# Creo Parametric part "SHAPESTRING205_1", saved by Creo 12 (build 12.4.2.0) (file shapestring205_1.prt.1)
Units: Custom; MM, KILOGRAM, SECS

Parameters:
  PTC_WM_ITERATION = "0"
  PTC_WM_VERSION = "-.0"
  PTC_WM_LIFECYCLE_STATE = "In Work"
  PTC_WM_LIFECYCLE = "MO_CADDocument"
  PTC_WM_CREATED_BY = "Maximilian Roepper (Z0017RMS: MO)"
  PTC_WM_CREATED_ON = "18-Sep-26 11:36:42 AM"
  PTC_WM_MODIFIED_BY = "Maximilian Roepper (Z0017RMS: MO)"
  PTC_WM_MODIFIED_ON = "18-Sep-26 11:36:46 AM"
  PDMLINKNUMBER = "PDM000071454910"
  PTC_WM_NAME = "shapestring205_1.prt"
  PTC_WM_NUMBER = "PDM000071454910"

Other parameters: WEIGHT, WEIGHT_FACTOR, WEIGHT_ADD, _MASS_TEMP, _DIFF_TEMP, MC_ERRORS, SUPPLIER

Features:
  1. coordinate system
  2. datum plane "PRT_YZ"
  3. datum plane "PRT_XY"
  4. datum plane "PRT_XZ"
  5. coordinate system
  6. datum axis
  7. datum axis
  8. datum axis
  9. coordinate system
  10. imported feature

Other named items: PRT, SIEMENS_MO, DRW_VIEW_ORG, PRT_X, PRT_Y, PRT_Z, CS0, ROUGH_GROB

Layers: 00_STD_CSYS-KSYS, 01_STD_PLANES-EBENEN, 02_STD_AXES-ACHSEN, 03_STD_CSYS-KSYS, 24_IMPORT_FEAT-IMPORT_KE, INTFCLR

Surfaces: 1 plane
